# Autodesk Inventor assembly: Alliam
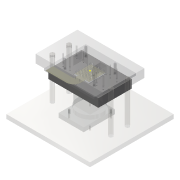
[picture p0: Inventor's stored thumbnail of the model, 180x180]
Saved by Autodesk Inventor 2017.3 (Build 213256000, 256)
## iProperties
Part Number: Alliam
Material: 一般
Document SubType Name: Assembly
Designer: kyushu-hep
Author: kyushu-hep
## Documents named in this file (8)
- C:\Users\kyushu-hep\Desktop\dkobayas\FlexAssembly3\Alliam.iam
- C:\Users\kyushu-hep\Desktop\dkobayas\FlexAssembly3\FlexBase.ipt
- C:\Users\kyushu-hep\Desktop\dkobayas\FlexAssembly3\ModuleBase.ipt
- C:\Users\kyushu-hep\Desktop\dkobayas\FlexAssembly3\Module.ipt
- C:\Users\kyushu-hep\Desktop\dkobayas\FlexAssembly3\FPC2.ipt
- C:\Users\kyushu-hep\Desktop\dkobayas\FlexAssembly3\base1.ipt
- C:\Users\kyushu-hep\Desktop\dkobayas\FlexAssembly3\ClearBoard.ipt
- C:\Users\kyushu-hep\Desktop\dkobayas\FlexAssembly3\Stages.ipt
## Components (7 placed, 7 different names)
1. FlexBase:1 — メイト:18, メイト:19, メイト:20, メイト:21, メイト:22, メイト:32, メイト:33
2. base1:1 — メイト:13, メイト:14, メイト:26, メイト:27, メイト:28, メイト:32, メイト:33
3. FPC2:1 — メイト:21, メイト:22, メイト:23
4. ModuleBase:1 — メイト:15, メイト:16, メイト:17, メイト:29, メイト:30, メイト:31
5. Module:1 — メイト:15, メイト:16, メイト:17
6. ClearBoard:1 — メイト:18, メイト:19, メイト:20, メイト:23
7. Stages:1 — メイト:26, メイト:27, メイト:28, メイト:29, メイト:30, メイト:31
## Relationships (19: Mate 19)
- メイト:13 [Mate]: base1:1
- メイト:14 [Mate]: base1:1
- メイト:15 [Mate]: ModuleBase:1 ↔ Module:1
- メイト:16 [Mate]: ModuleBase:1 ↔ Module:1
- メイト:17 [Mate]: ModuleBase:1 ↔ Module:1
- メイト:18 [Mate]: FlexBase:1 ↔ ClearBoard:1
- メイト:19 [Mate]: FlexBase:1 ↔ ClearBoard:1
- メイト:20 [Mate]: FlexBase:1 ↔ ClearBoard:1
- メイト:21 [Mate]: FlexBase:1 ↔ FPC2:1
- メイト:22 [Mate]: FlexBase:1 ↔ FPC2:1
- メイト:23 [Mate]: FPC2:1 ↔ ClearBoard:1
- メイト:26 [Mate]: base1:1 ↔ Stages:1
- メイト:27 [Mate]: base1:1 ↔ Stages:1
- メイト:28 [Mate]: base1:1 ↔ Stages:1
- メイト:29 [Mate]: ModuleBase:1 ↔ Stages:1
- メイト:30 [Mate]: ModuleBase:1 ↔ Stages:1
- メイト:31 [Mate]: ModuleBase:1 ↔ Stages:1
- メイト:32 [Mate]: FlexBase:1 ↔ base1:1
- メイト:33 [Mate]: FlexBase:1 ↔ base1:1
